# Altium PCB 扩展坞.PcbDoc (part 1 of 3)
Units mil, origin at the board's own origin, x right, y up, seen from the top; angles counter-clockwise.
Board outline 3543.31 x 1968.5 mil, 4 copper layers (Top Layer 1, Layer1, Layer2, Bottom Layer 1), stack 62.337 mil thick; 191 components, 182 nets, 737 pads, 256 vias.
Unrouted connection lines stored in the file: 242.
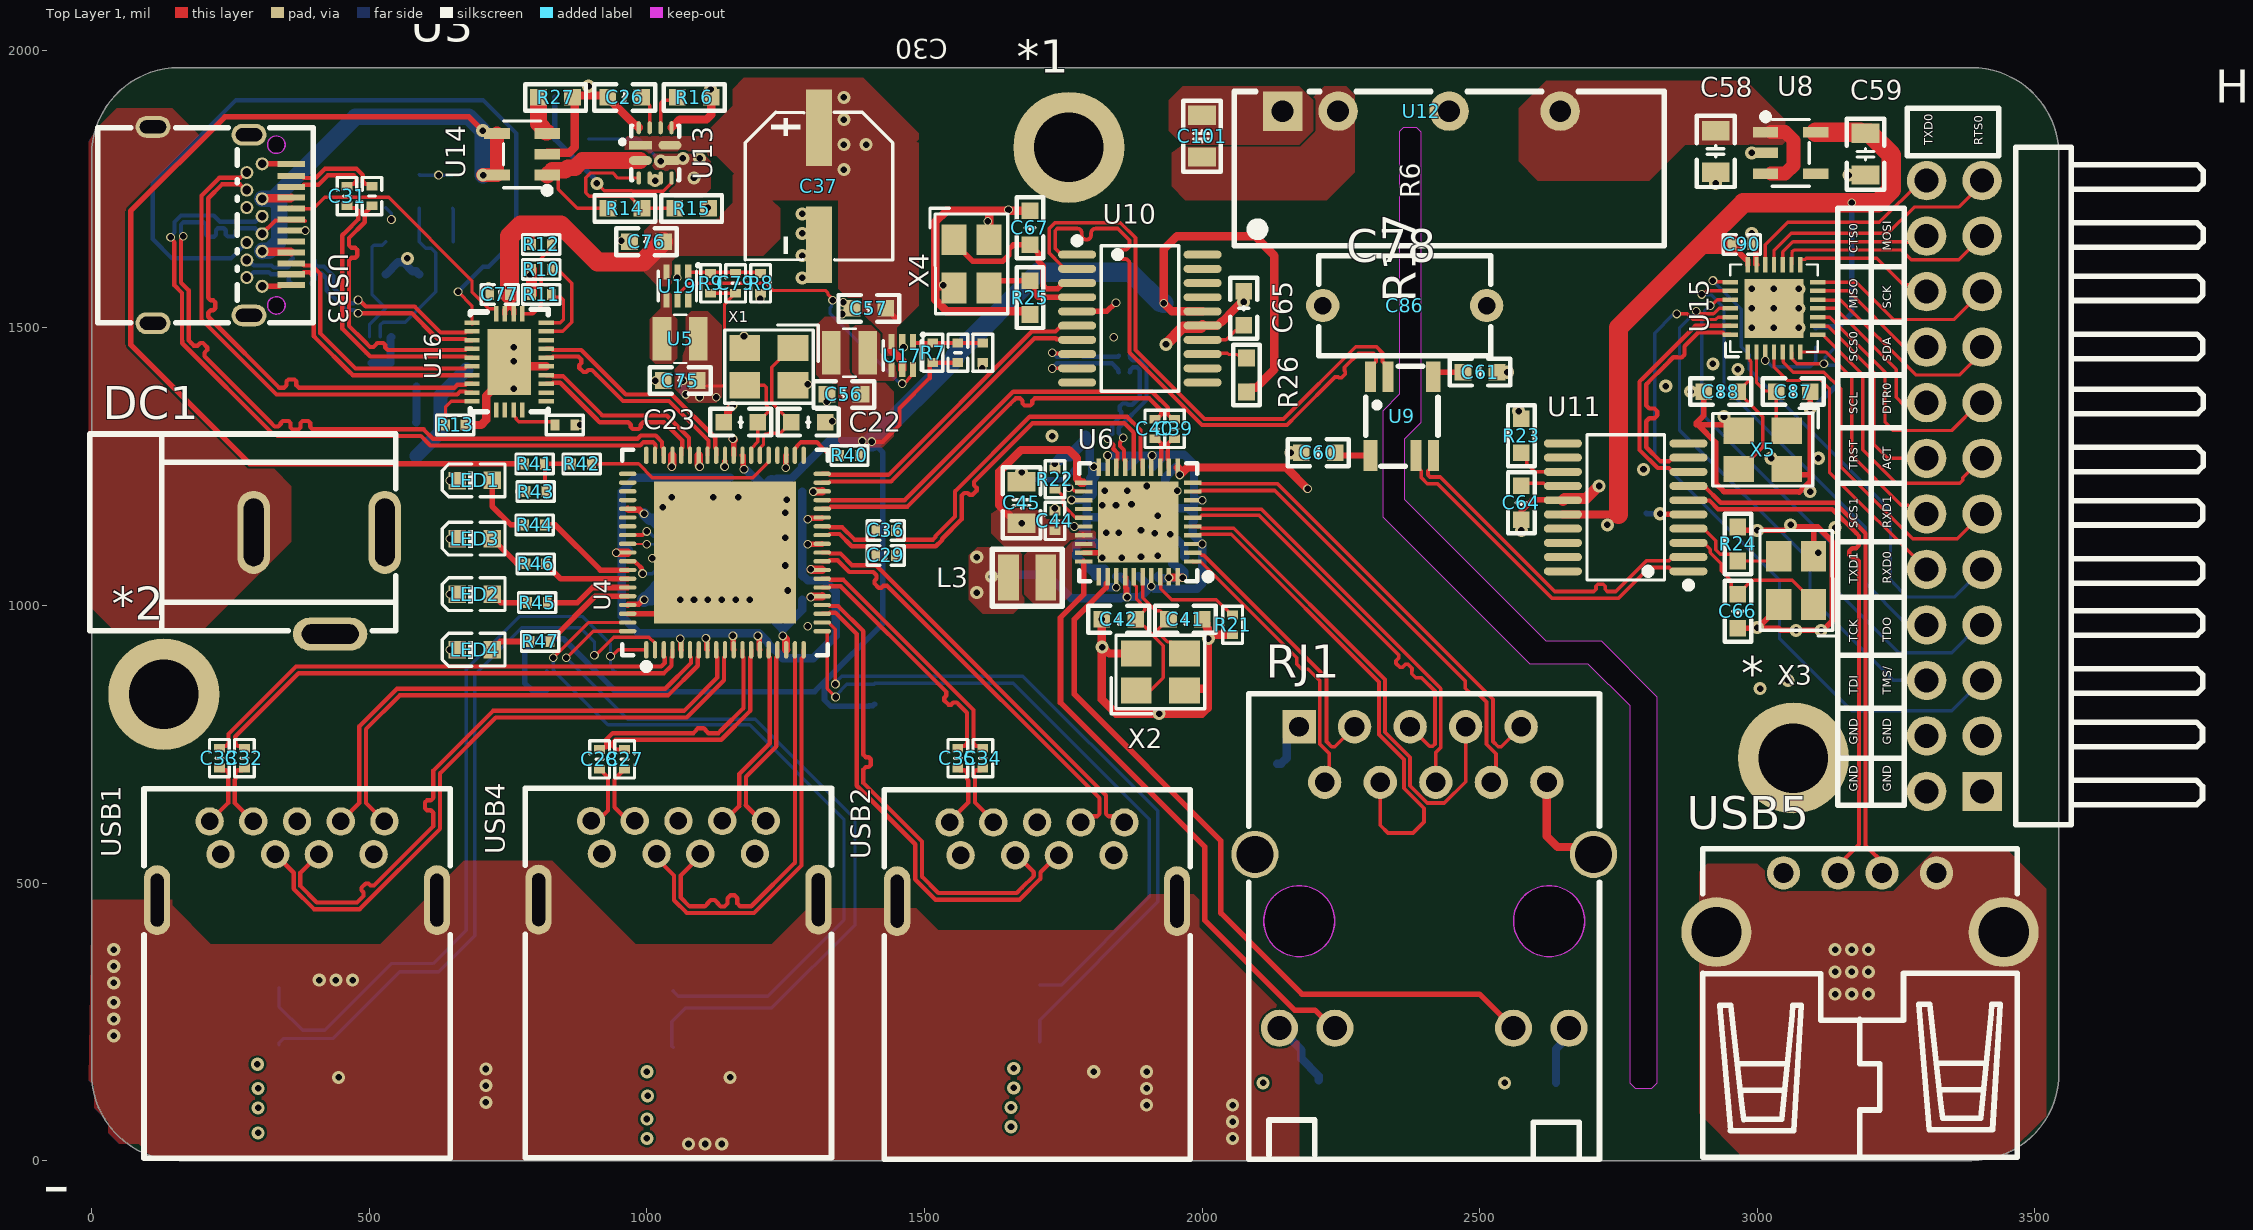
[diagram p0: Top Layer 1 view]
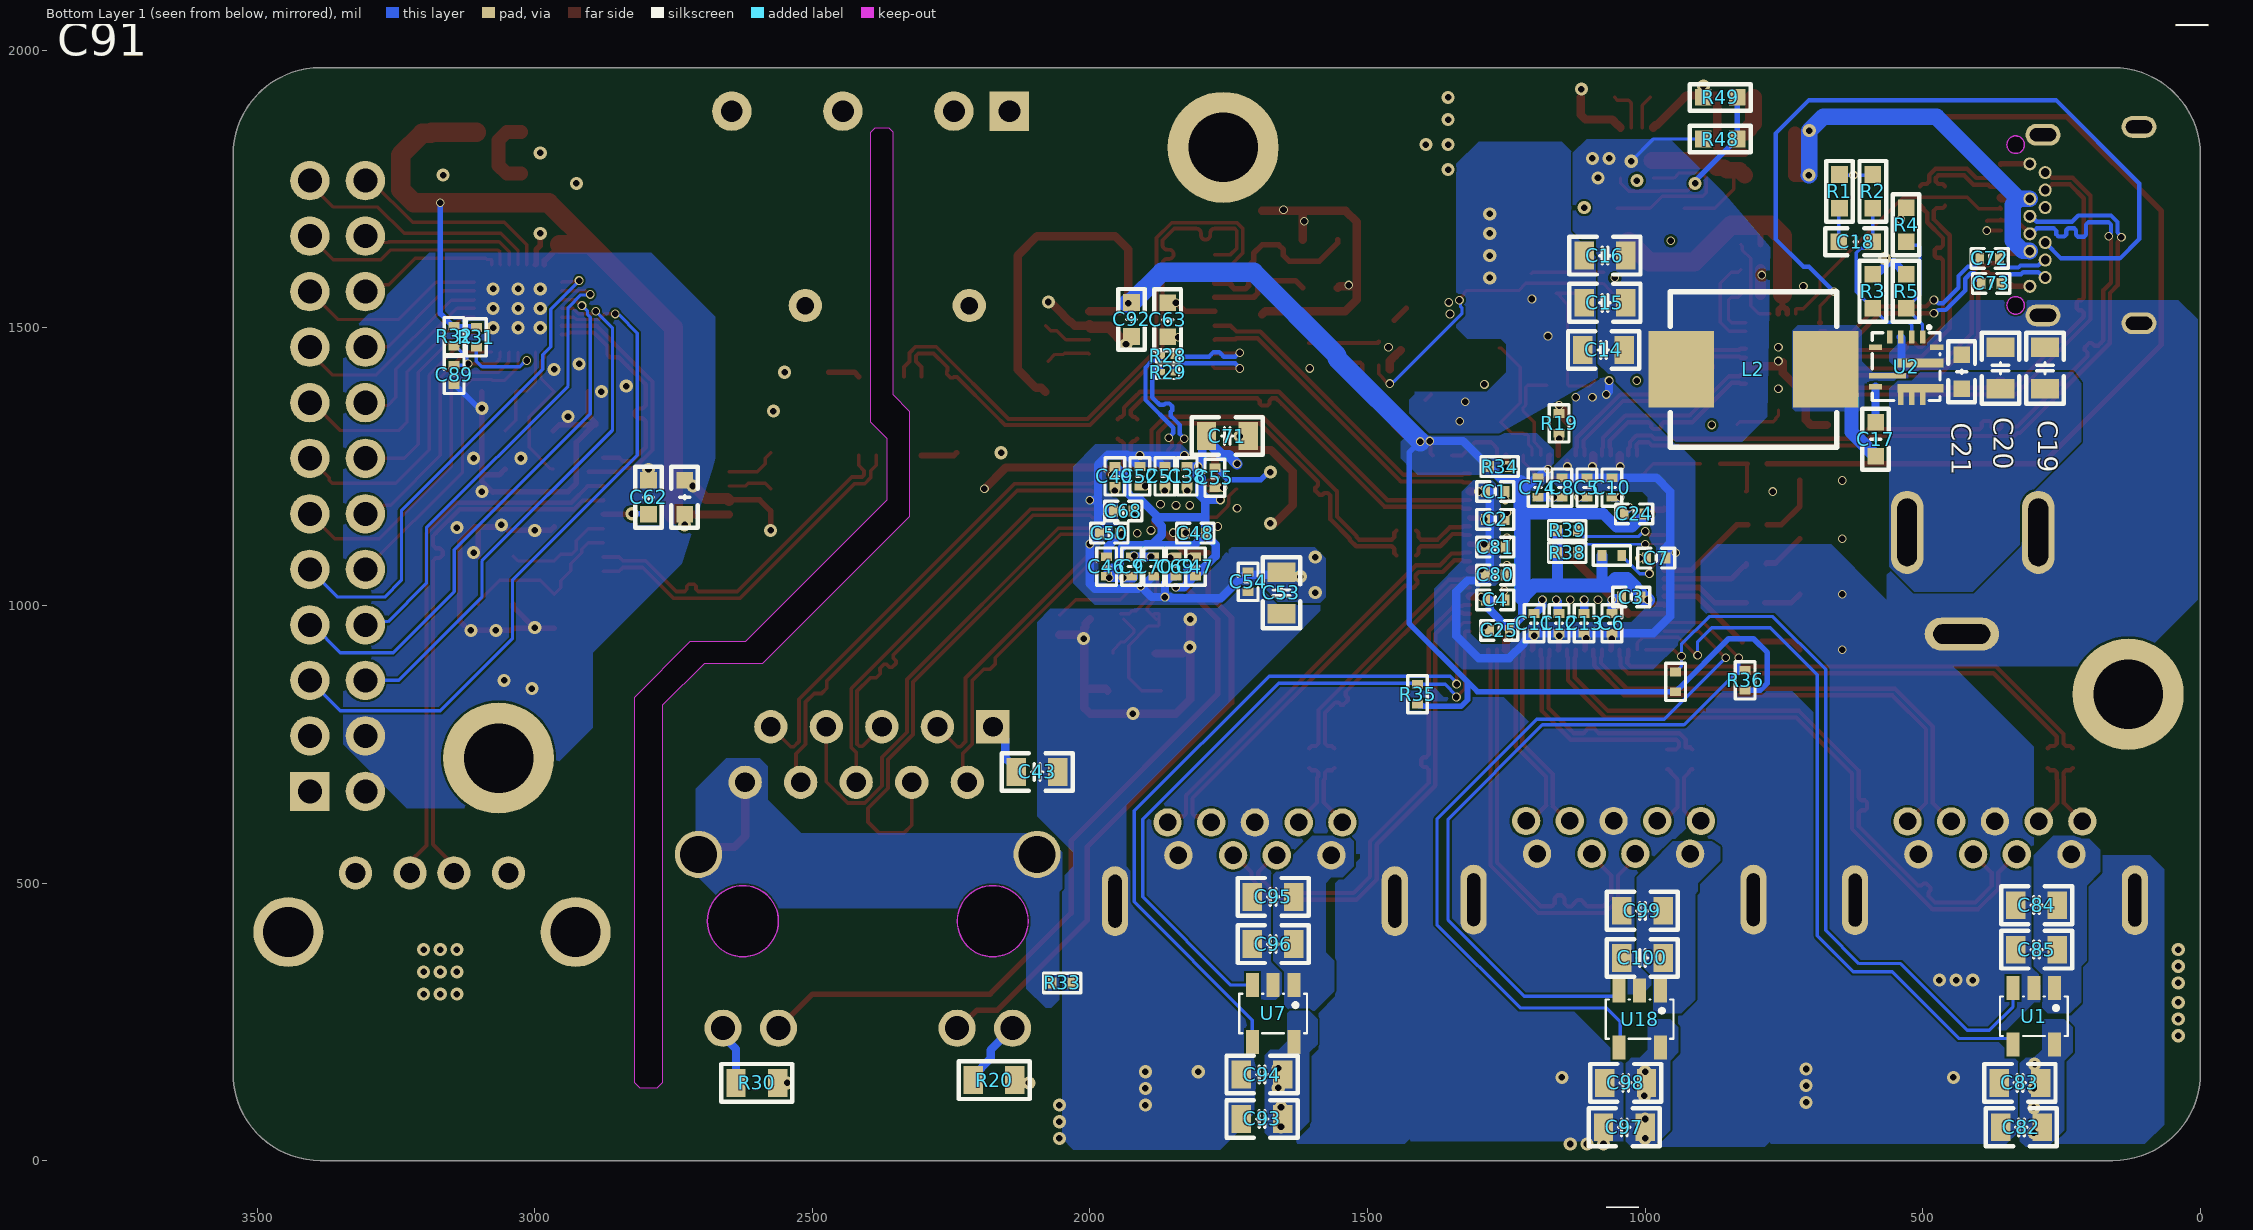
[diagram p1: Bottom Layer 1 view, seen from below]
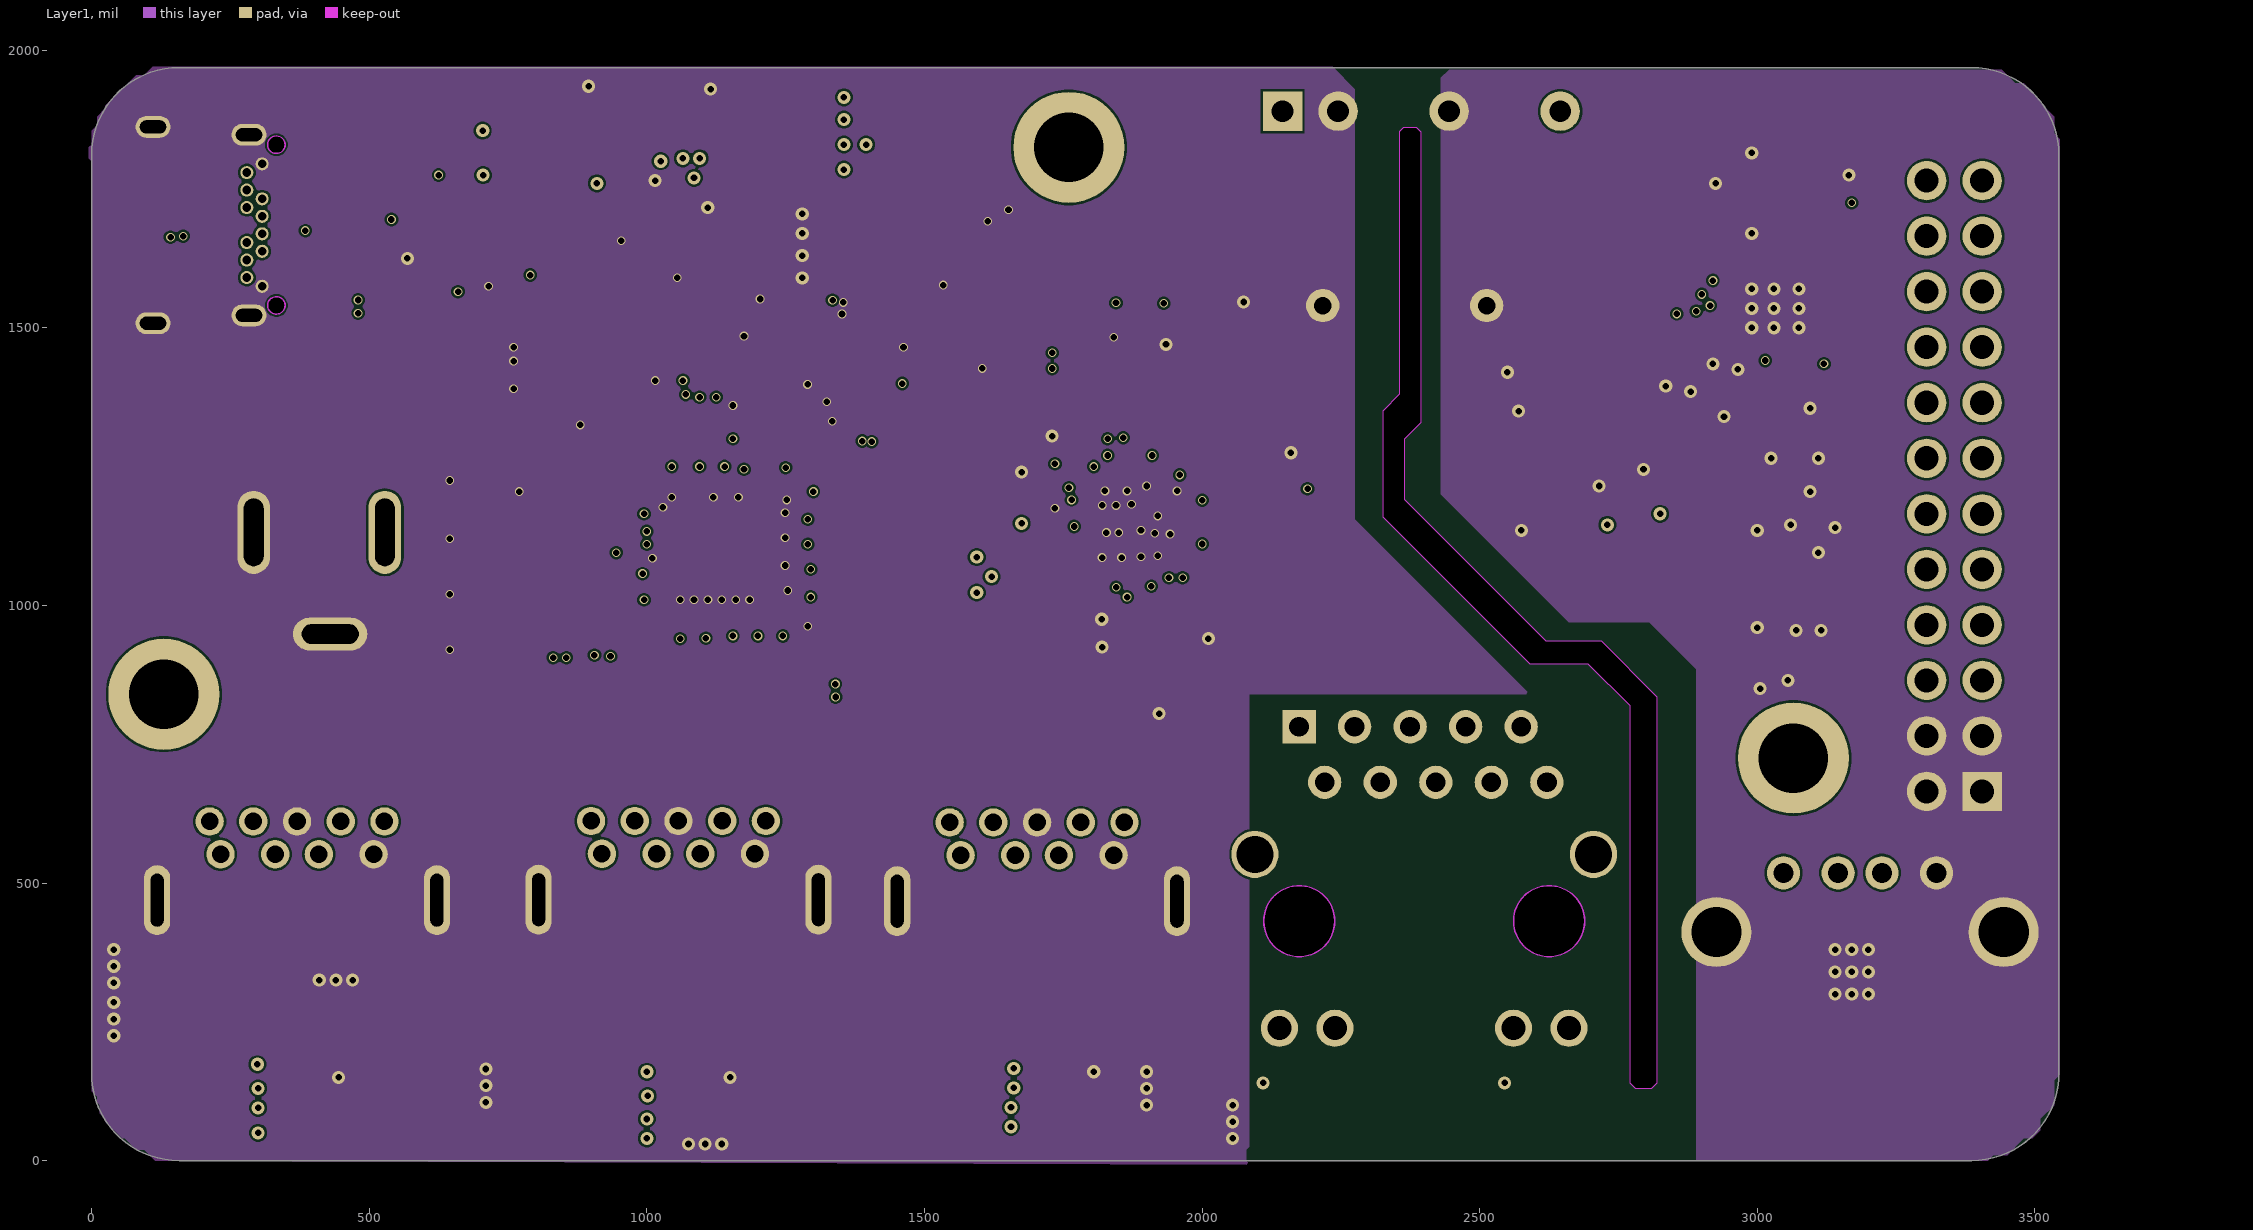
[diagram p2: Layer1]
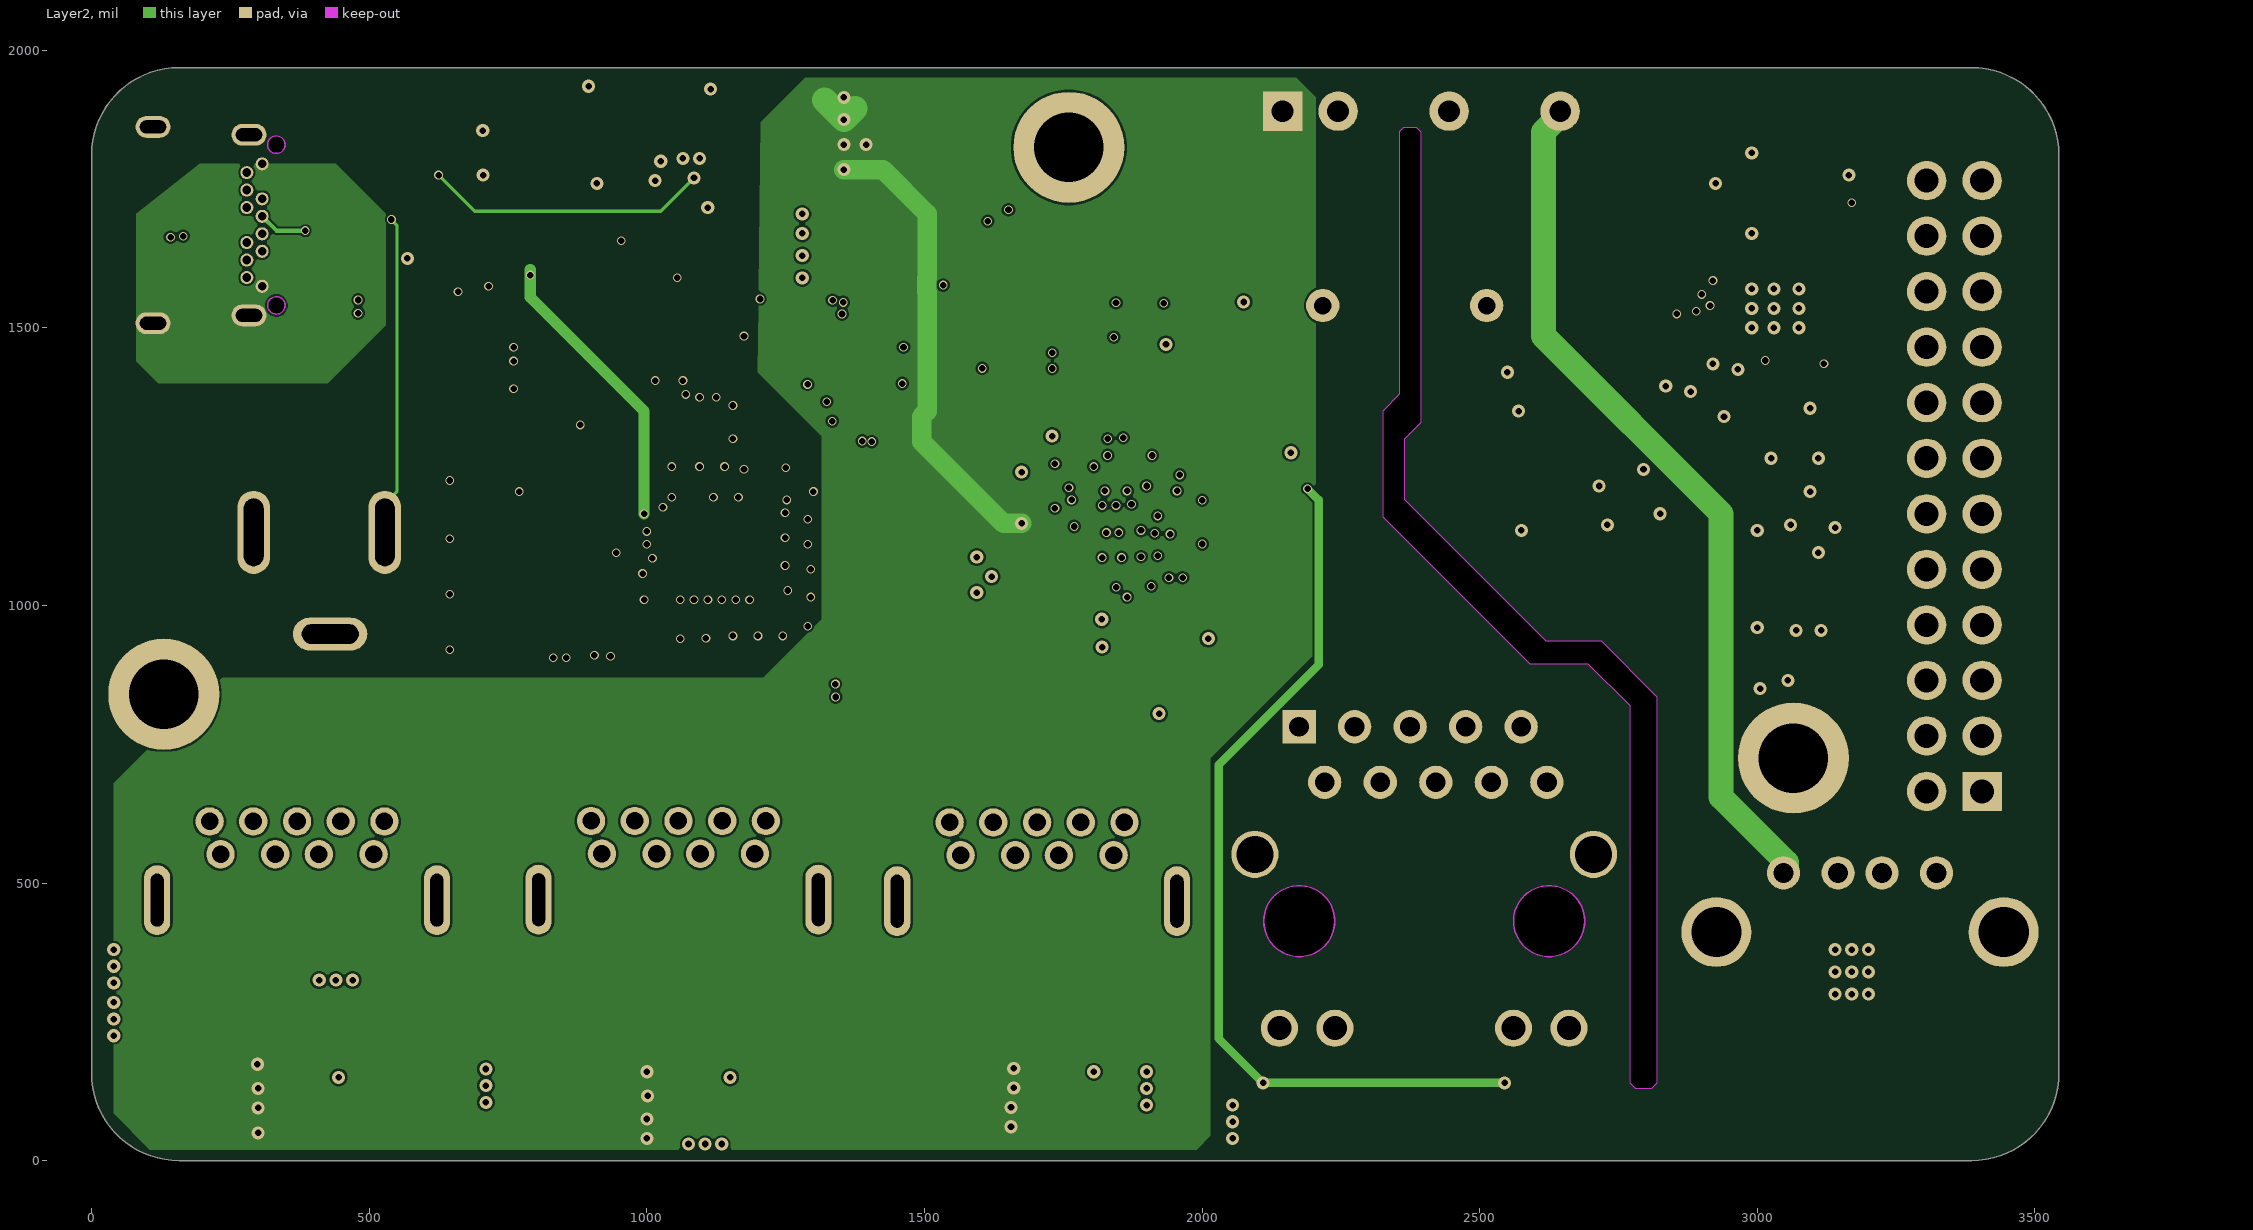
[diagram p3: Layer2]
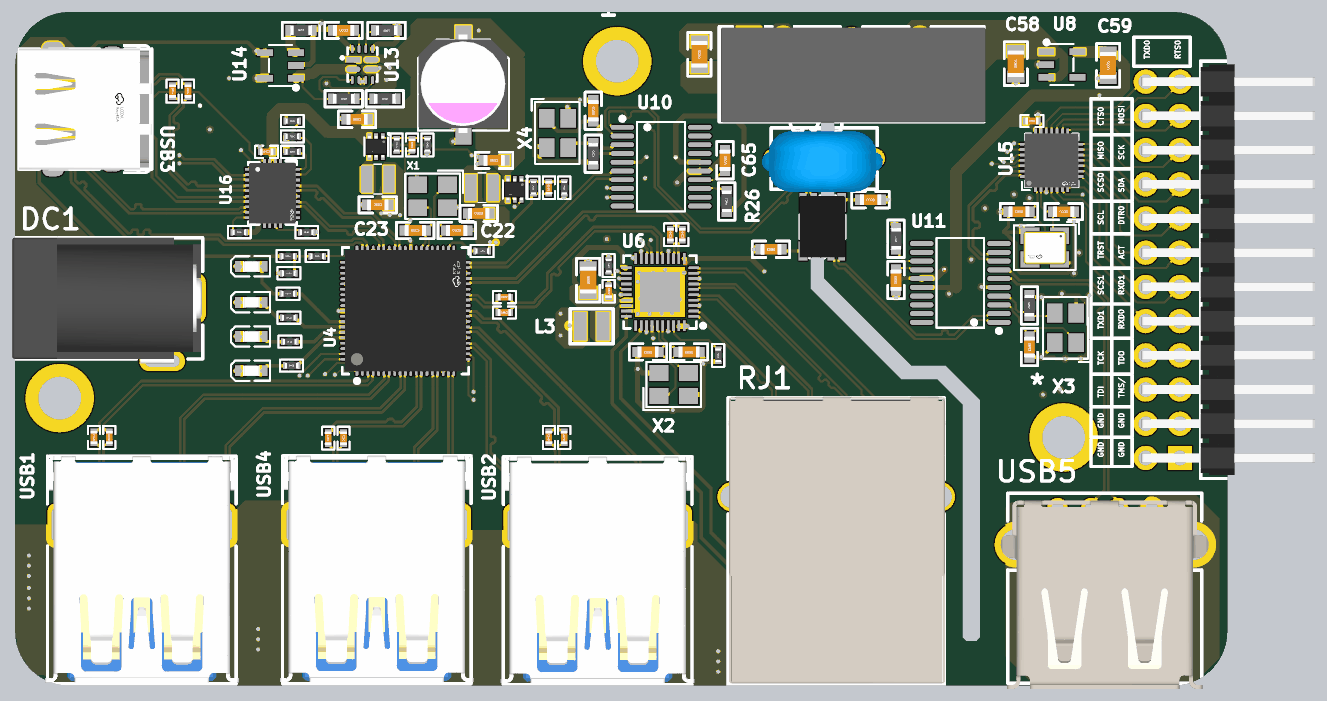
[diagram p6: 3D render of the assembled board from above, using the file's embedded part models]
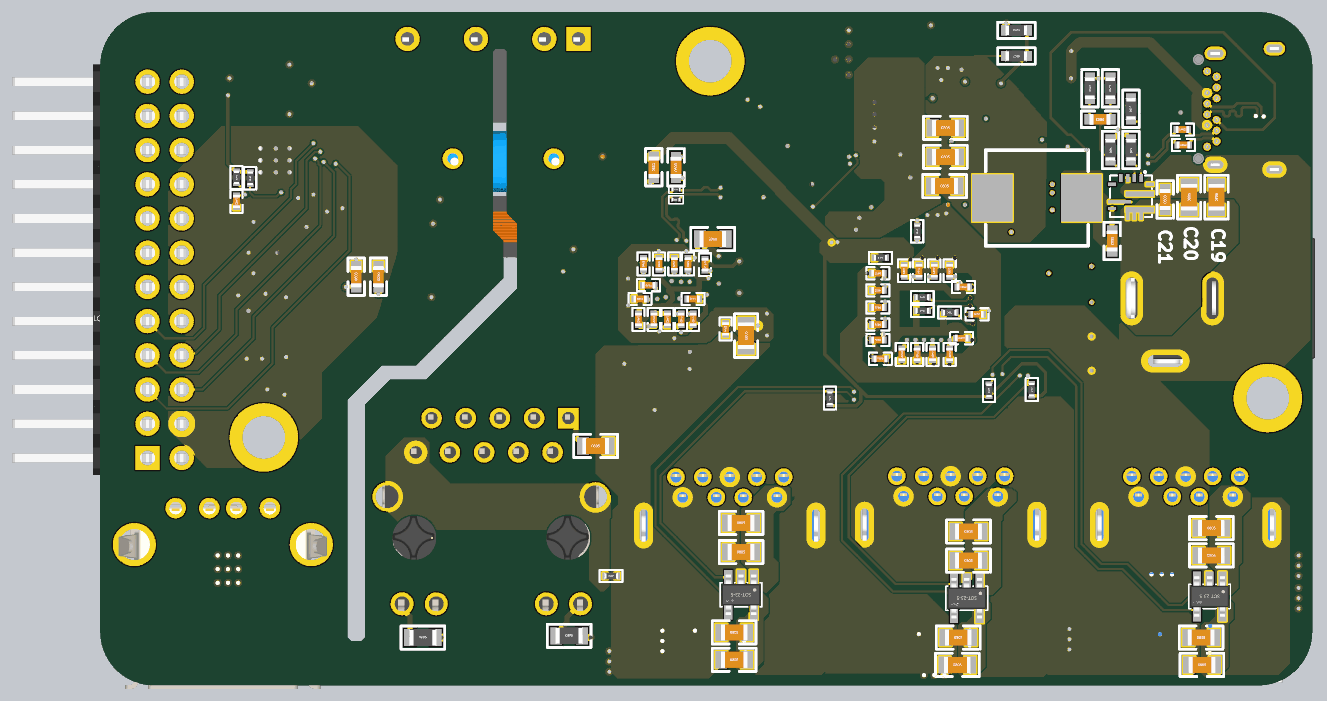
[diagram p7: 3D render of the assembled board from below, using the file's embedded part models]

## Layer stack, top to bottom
Top Solder: solder mask 0.4, Solder Resist, Dk 3.5
Top Layer 1: signal copper 1.378
Dielectric 2: prepreg 2.8, PP-006, Dk 4.1
Layer1: signal copper 1.4
Dielectric 1: dielectric 51.1811, FR-4, Dk 4.8
Layer2: signal copper 1.4
Dielectric 3: prepreg 2.8, PP-006, Dk 4.1
Bottom Layer 1: signal copper 1.378
Bottom Solder: solder mask 0.4, Solder Resist, Dk 3.5

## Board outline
0,157.48 0,1811.02 cw(c157.48,1811.02) 157.48,1968.5 3385.83,1968.5 cw(c3385.83,1811.02) 3543.31,1811.02 3543.31,157.48 cw(c3385.83,157.48) 3385.83,0 157.48,0 cw(c157.48,157.48)
cut-out: 2365,1240 2365,1300 2395,1330 2395,1852.09 2387.09,1860 2362.09,1860 2355,1852.91 2355,1380 2325,1350 2325,1160 2590,895 2695,895 2770,820 2770,140 2780,130 2810,130 2820,140 2820,835 2720,935 2620,935 2365,1190

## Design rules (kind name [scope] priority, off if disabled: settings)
Clearance [All] p1: gap=4 ignorepadtopadclearanceinfootprint=FALSE except(0: Arc-Hole Track-Hole SMDPad-Hole THPad-Hole Via-Hole Fill-Hole Poly-Hole Region-Hole Text-Hole)
ComponentClearance [All] p1: gap=4 collisioncheckmode=3 verticalgap=10 showdistances=FALSE
DiffPairsRouting DiffPair_DiffPairsRouting [InDifferentialPair('No Differential Pair')] p1: maxlimit=30 minlimit=10 mostfreqgap=10 toplayer_minwidth=15 toplayer_maxwidth=30 toplayer_prefwidth=15 midlayer1_minwidth=15 midlayer1_maxwidth=30 midlayer1_prefwidth=15 midlayer2_minwidth=15 midlayer2_maxwidth=30 midlayer2_prefwidth=15 bottomlayer_minwidth=15 bottomlayer_maxwidth=30 bottomlayer_prefwidth=15 maxuncoupledlength=500
DiffPairsRouting DiffPairsRouting_90 [InDifferentialPairClass('90ohm')] p2: maxlimit=40 minlimit=4 mostfreqgap=4.26 toplayer_minwidth=4 toplayer_maxwidth=30 toplayer_prefwidth=7.74 midlayer1_minwidth=4 midlayer1_maxwidth=30 midlayer1_prefwidth=7.74 midlayer2_minwidth=4 midlayer2_maxwidth=30 midlayer2_prefwidth=7.74 bottomlayer_minwidth=4 bottomlayer_maxwidth=30 bottomlayer_prefwidth=7.74 maxuncoupledlength=500
DiffPairsRouting DiffPairsRouting_100 [InDifferentialPairClass('100ohm')] p3: maxlimit=10 minlimit=4 mostfreqgap=10 toplayer_prefgap=5.3 toplayer_minwidth=4 toplayer_maxwidth=30 toplayer_prefwidth=6.7 midlayer1_mingap=10 midlayer1_minwidth=15 midlayer1_maxwidth=15 midlayer1_prefwidth=15 midlayer2_mingap=10 midlayer2_minwidth=15 midlayer2_maxwidth=15 midlayer2_prefwidth=15 bottomlayer_prefgap=5.3 bottomlayer_minwidth=4 bottomlayer_maxwidth=30 bottomlayer_prefwidth=6.7 maxuncoupledlength=500
HoleSize [All] p1: absolutevalues=TRUE maxlimit=500 minlimit=1 maxpercent=80.000 minpercent=20.000
HoleToHoleClearance [All] p1: gap=10 allowstackedmicrovias=FALSE
MatchedLengths [InDifferentialPairClass('90ohm')] p1: tolerance=5 checknetsindiffpair=TRUE checkdiffpairvsdiffpair=FALSE checkxsignals=FALSE checkothers=FALSE
MatchedLengths DiffPair_MatchedLengths [InDifferentialPairClass('100ohm')] p2: tolerance=5 checknetsindiffpair=TRUE checkdiffpairvsdiffpair=FALSE checkxsignals=FALSE checkothers=FALSE
MinimumSolderMaskSliver [All] p1: minsoldermaskwidth=0
PolygonConnect [All] p1: connectstyle=Direct reliefconductorwidth=10 reliefentries=4 polygonreliefangle="90 Angle" airgapwidth=10
RoutingVias [All] p1: holewidth=11.81 width=15.75 viastyle="Through Hole" minholewidth=11.81 minwidth=15.75 maxholewidth=23.62 maxwidth=50
SilkToSolderMaskClearance [IsPad] p1: minsilkscreentomaskgap=2 clearancetoexposedcopper=TRUE
SolderMaskExpansion [All] p1: expansion=4 istentingtop=FALSE
Width [All] p1: maxlimit=100 minlimit=4 preferedwidth=10 minimp=50.000000 maximp=50.000000 favimp=50.000000
24 further rules are at their usual default settings.

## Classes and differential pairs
differential pair class 100ohm: HS2 INX MDI0 MDI1 MDI2 MDI3 NewDifferentialPair2 X X_IN
differential pair class 90ohm: AC_SS2_RX AC_SS2_TX AC_SS3_TX AC_SS4_TX AC_TX1 AC_UP_TX DU DU2 ETH ETH1 ETH1_D ETH_D HS2 HSD0 HSD1 HSD2 HSD3 HSD4 ISO_USB1 ISO_USB2 NewDifferentialPair2 P1C_SS_RX P1C_SS_TX RX0 RX1 RX2 RX3 RX4 SS1_RX SS1_TX SS2_RX SS2_TX SS3_RX SS3_TX SS4_RX SS4_TX TX0 TX1 TX2 TX3 TX4 UP_RX UP_TX
component class ISO_USB: C58 C59 C60 C61 C62 C63 C64 C65 C66 C67 C86 C87 C88 C89 C90 C91 C92 C101 H1 R23 R24 R25 R26 R31 R32 U8 U9 U10 U11 U12 U15 USB5 X3 X4 X5
component class ETH: C9 C29 C36 C38 C39 C40 C41 C42 C43 C44 C45 C46 C47 C48 C49 C50 C51 C52 C53 C54 C55 C68 C69 C70 C71 L3 R20 R21 R22 R28 R29 R30 R33 RJ1 U6 X2
component class Power: C14 C15 C16 C17 C18 C19 C20 C21 C26 C37 C56 C57 C75 C76 C78 C79 DC1 L2 R1 R2 R3 R4 R5 R6 R7 R8 R9 R14 R15 R16 R27 R48 R49 U2 U4 U5 U13 U14 U17 U19
component class VL822: * *1 *2 C1 C2 C3 C4 C5 C6 C7 C8 C10 C11 C12 C13 C22 C23 C24 C25 C27 C28 C30 C31 C32 C33 C34 C35 C72 C73 C74 C77 C80 C81 C82 C83 C84 C85 C93 C94 C95 C96 C97 C98 C99 C100 LED1 LED2 LED3 LED4 R10 R11 R12 R13 R17 R18 R19 R34 R35 R36 R37 R38 R39 R40 R41 R42 R43 R44 R45 R46 R47 U1 U3 U7 U16 U18 USB1 USB2 USB3 USB4 X1
differential pair NewDifferentialPair1: +AC_SS1_TX_P -AC_SS1_TX_N
differential pair X: +X_P -X_N
differential pair TX4: +TX4_P -TX4_N
differential pair TX3: +TX3_P -TX3_N
differential pair TX2: +TX2_P -TX2_N
differential pair TX1: +TX1_P -TX1_N
differential pair RX4: +RX4_P -RX4_N
differential pair RX3: +RX3_P -RX3_N
differential pair RX2: +RX2_P -RX2_N
differential pair RX1: +RX1_P -RX1_N
differential pair INX: +INX_P -INX_N
differential pair HSD4: +HSD4_P -HSD4_N
differential pair HSD3: +HSD3_P -HSD3_N
differential pair HSD2: +HSD2_P -HSD2_N
differential pair HSD1: +HSD1_P -HSD1_N
differential pair ETH_D: +ETH_D_P -ETH_D_N
differential pair ETH1_D: +ETH1_D_P -ETH1_D_N
differential pair DU: +DU_P -DU_N
differential pair DU2: +DU2_P -DU2_N
differential pair AC_TX1: +AC_TX1_P -AC_TX1_N
differential pair TX0: +TX0_P -TX0_N
differential pair RX0: +RX0_P -RX0_N
differential pair HSD0: +HSD0_P -HSD0_N
differential pair MDI3: +MDI3_P -MDI3_N
differential pair MDI2: +MDI2_P -MDI2_N
differential pair MDI1: +MDI1_P -MDI1_N
differential pair MDI0: +MDI0_P -MDI0_N
differential pair AC_SS2_TX: +AC_SS2_TX_P -AC_SS2_TX_N
differential pair AC_SS2_RX: +AC_SS2_RX_P -AC_SS2_RX_N
differential pair AC_SS4_TX: +AC_SS4_TX_P -AC_SS4_TX_N
differential pair AC_SS3_TX: +AC_SS3_TX_P -AC_SS3_TX_N
differential pair SS1_RX: +SS1_RX_P -SS1_RX_N
differential pair P1C_SS_RX: +P1C_SS_RX_P -P1C_SS_RX_N
differential pair SS1_TX: +SS1_TX_P -SS1_TX_N
differential pair AC_PC1_TX: +AC_P1C_SS_TX_P -AC_P1C_SS_TX_N
differential pair P1C_SS_TX: +P1C_SS_TX_P -P1C_SS_TX_N

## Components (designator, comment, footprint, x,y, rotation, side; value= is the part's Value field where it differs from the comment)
* "M3" "M3 125X200" 3065,725 r0 top
*1 "M3" "M3 125X200" 1760,1825 r0 top
*2 "M3" "M3 125X200" 130,840 r0 top
C1 "100nF" "C 0402_L" 1270,1205 r0 bottom
C2 "100nF" "C 0402_L" 1270,1155 r0 bottom
C3 "100nF" "C 0402_L" 1025,1015 r180 bottom
C4 "100nF" "C 0402_L" 1270,1010 r0 bottom
C5 "100nF" "C 0402_L" 1105,1212.29 r90 bottom
C6 "100nF" "C 0402_L" 1060,967.71 r270 bottom
C7 "100nF" "C 0402_L" 980,1085 r180 bottom
C8 "100nF" "C 0402_L" 1150,1212.29 r90 bottom
C9 "100nF" "C 0402_L" 1925,1070 r270 bottom
C10 "100nF" "C 0402_L" 1060,1212.29 r90 bottom
C11 "100nF" "C 0402_L" 1200,967.71 r270 bottom
C12 "100nF" "C 0402_L" 1155,967.71 r270 bottom
C13 "100nF" "C 0402_L" 1110,967.71 r270 bottom
C14 "22uF" "C 0805_L" 1075,1460 r180 bottom
C15 "22uF" "C 0805_L" 1072.4,1545 r180 bottom
C16 "22uF" "C 0805_L" 1072.4,1630 r180 bottom
C17 "100nF" "C 0603_L" 585,1299.41 r270 bottom
C18 "100pF" "C 0603_L" 620.59,1655 r0 bottom
C19 "10uF" "C 0805_L" 280,1427.4 r90 bottom
C20 "10uF" "C 0805_L" 360,1427.4 r90 bottom
C21 "100nF" "C 0603_L" 430,1420.59 r90 bottom
C22 "20pF" "C 0603_L" 1290.59,1330 r0 top
C23 "20pF" "C 0603_L" 1169.41,1330 r0 top
C24 "100nF" "C 0402_L" 1020,1165 r180 bottom
C25 "100nF" "C 0402_L" 1262.71,955 r180 bottom
C26 "100nF" "C 0603_L" 960,1915 r0 top
C27 "100nF" "C 0402_L" 960,722.72 r90 top
C28 "100nF" "C 0402_L" 915,722.72 r90 top
C29 "100nF" "C 0402_L" 1430,1090 r0 top
C30 "100nF" "C 0402_L" 505,1737.28 r270 top
C31 "100nF" "C 0402_L" 460,1737.28 r270 top
C32 "100nF" "C 0402_L" 275,725 r90 top
C33 "100nF" "C 0402_L" 230,725 r90 top
C34 "100nF" "C 0402_L" 1605,725 r90 top
C35 "100nF" "C 0402_L" 1560,725 r90 top
C36 "100nF" "C 0402_L" 1430,1135 r0 top
C37 "ma25v220m6x8" CAP-SMD_BD6.3-L6.6-W6.6-LS7.3-FD 1310,1755 r270 top value=220uF
C38 "100nF" "C 0402_L" 1825,1232.29 r90 bottom
C39 "100nF" "C 0402_L" 1950,1317.71 r270 top
C40 "100nF" "C 0402_L" 1915,1317.71 r270 top
C41 "20pF" "C 0603_L" 1970,975 r180 top
C42 "20pF" "C 0603_L" 1850,975 r180 top
C43 "100nF" "C 0805_L" 2095,700 r180 bottom
C44 "100nF" "C 0402_L" 1735,1152.28 r270 top
C45 "10uF" "C 0805_L" 1675,1185 r270 top
C46 "100nF" "C 0402_L" 1970,1070 r270 bottom
C47 "100nF" "C 0402_L" 1810,1070 r270 bottom
C48 "100nF" "C 0402_L" 1810,1130 r180 bottom
C49 "100nF" "C 0402_L" 1955,1232.29 r90 bottom
C50 "100nF" "C 0402_L" 1965,1130 r0 bottom
C51 "100nF" "C 0402_L" 1865,1232.29 r90 bottom
C52 "100nF" "C 0402_L" 1910,1232.29 r90 bottom
C53 "10uF" "C 0805_L" 1655,1022.6 r90 bottom
C54 "100nF" "C 0402_L" 1715,1042.29 r90 bottom
C55 "100nF" "C 0402_L" 1775,1230 r270 bottom
C56 "22uF" "C 0603_L" 1355,1380 r0 top
C57 "22uF" "C 0603_L" 1400,1535 r0 top
C58 "10uF" "C 0805_L" 2925,1817.6 r90 top
C59 "10uF" "C 0805_L" 3195,1812.6 r90 top
C60 "100nF" "C 0603_L" 2209.41,1275 r180 top
C61 "100nF" "C 0603_L" 2500.59,1420 r180 top
C62 "1uF" "C 0603_L" 2795,1195 r90 bottom
C63 "1uF" "C 0603_L" 1860,1514.41 r90 bottom
C64 "100nF" "C 0603_L" 2575,1185 r90 top
C65 "100nF" "C 0603_L" 2075,1535 r270 top
C66 "30pF" "C 0603_L" 2965,989.41 r270 top
C67 "30pF" "C 0603_L" 1690,1680 r90 top
C68 "100nF" "C 0402_L" 1940,1170 r0 bottom
C69 "100nF" "C 0402_L" 1845,1070 r270 bottom
C70 "100nF" "C 0402_L" 1885,1070 r270 bottom
C71 "10uF" "C 0805_L" 1752.6,1305 r0 bottom
C72 "100nF" "C 0402_L" 379.6,1625 r180 bottom
C73 "100nF" "C 0402_L" 376.88,1580 r180 bottom
C74 "100nF" "C 0402_L" 1193.03,1212.29 r90 bottom
C75 "22uF" "C 0603_L" 1060,1405 r0 top
C76 "22uF" "C 0603_L" 999.41,1655 r0 top
C77 "100nF" "C 0402_L" 735,1560 r0 top
C78 "22pF" "C 0402_L" 1560,1455 r90 top
C79 "22pF" "C 0402_L" 1160,1580 r90 top
C80 "100nF" "C 0402_L" 1270,1055 r0 bottom
C81 "100nF" "C 0402_L" 1270,1105 r0 bottom
C82 "22uF" "C 0805_L" 322.4,60 r180 bottom
C83 "22uF" "C 0805_L" 325,140 r180 bottom
C84 "22uF" "C 0805_L" 295,460 r180 bottom
C85 "22uF" "C 0805_L" 295,380 r180 bottom
C86 "q222m060110fq55250l7579" CAP-TH_L8.0-W4.5-P7.50-D0.6 2365,1540 r0 top value=2.2nF
C87 "20pF" "C 0603_L" 3065,1385 r180 top
C88 "20pF" "C 0603_L" 2934.41,1385 r180 top
C89 "100nF" "C 0402_L" 3145,1415 r270 bottom
C90 "100nF" "C 0402_L" 2972.28,1650 r180 top
C91 "100nF" "C 0603_L" 2730,1195 r270 bottom
C92 "100nF" "C 0603_L" 1925,1515 r90 bottom
C93 "22uF" "C 0805_L" 1690,75 r180 bottom
C94 "22uF" "C 0805_L" 1690,155 r180 bottom
C95 "22uF" "C 0805_L" 1670,475 r180 bottom
C96 "22uF" "C 0805_L" 1670,390 r180 bottom
C97 "22uF" "C 0805_L" 1037.6,60 r180 bottom
C98 "22uF" "C 0805_L" 1035,140 r180 bottom
C99 "22uF" "C 0805_L" 1005,450 r180 bottom
C100 "22uF" "C 0805_L" 1005,365 r180 bottom
C101 "10uF" "C 0805_L" 2000,1845 r90 top
DC1 "dc-005-a200" DC-IN-TH_DC-005-A200 410,1040 r0 top
H1 "x6521wr-2x12h-c60d30" HDR-TH_24P-P2.54-H-M-R2-C12-S2.54 3355,1215 r90 top
L2 "pcr0630-3r3-m" IND-SMD_L7.5-W6.6 805,1425 r0 bottom
L3 "smms252012-2r2m" IND-SMD_L2.5-W2.0_AFE252010S 1685,1050 r180 top value=2.2uH
LED1 "f.0603.00025/p2-0603g1ts2-06t-002" LED0603-RD_GREEN 690,1225 r0 top
LED2 "f.0603.00025/p2-0603g1ts2-06t-002" LED0603-RD_GREEN 690,1020 r0 top
LED3 "f.0603.00025/p2-0603g1ts2-06t-002" LED0603-RD_GREEN 690,1120 r0 top
LED4 "f.0603.00025/p2-0603g1ts2-06t-002" LED0603-RD_GREEN 690,920 r0 top
R1 "20K" "R 0603_L" 650,1745.59 r270 bottom
R2 "110K" "R 0603_L" 590,1745.59 r90 bottom
R3 "15K" "R 0603_L" 590,1565.59 r270 bottom
R4 "169K" "R 0603_L" 530,1685.59 r90 bottom
R5 "36.1K" "R 0603_L" 530,1565.59 r270 bottom
R6 "100K" "R 0402_L" 1605,1455 r270 top
R7 "450K" "R 0402_L" 1515,1455 r90 top
R8 "100k" "R 0402_L" 1205,1580 r270 top
R9 "75K" "R 0402_L" 1115,1580 r90 top
R10 "10K" "R 0402_L" 810,1605 r180 top
R11 "10K" "R 0402_L" 810,1560 r180 top
R12 "10K" "R 0402_L" 810,1650 r180 top
R13 "20.5K" "R 0402_L" 655,1325 r180 top
R14 "10K" "R 0603_L" 960.59,1715 r180 top
R15 "3.3K" "R 0603_L" 1080.59,1715 r180 top
R16 "0R" "R 0603_L" 1085.59,1915 r180 top
R17 "10K" "R 0402_L" 852.28,1325 r180 top
R18 "4.7K" "R 0402_L" 945,862.29 r90 bottom
R19 "12.4K" "R 0402_L" 1155,1327.71 r270 bottom
R20 "1K" "R 0805_L" 2172.6,145 r180 bottom
R21 "2.49K" "R 0402_L" 2055,965 r90 top
R22 "10K" "R 0402_L" 1735,1227.28 r270 top
R23 "5.1K" "R 0603_L" 2575,1305.59 r90 top
R24 "4.7M" "R 0603_L" 2965,1110.59 r90 top
R25 "4.7M" "R 0603_L" 1690,1554.41 r270 top
R26 "5.1K" "R 0603_L" 2080,1415 r90 top
R27 "10K" "R 0603_L" 835.59,1915 r0 top
R28 "0R" "R 0201_L" 1859.84,1450 r180 bottom
R29 "0R" "R 0201_L" 1860,1420 r180 bottom
R30 "1K" "R 0805_L" 2600,140 r180 bottom
R31 "10K" "R 0402_L" 3105,1482.71 r270 bottom
R32 "0R" "R 0402_L" 3145,1485 r270 bottom
R33 "0R" "R 0402_L" 2050,320 r180 bottom
R34 "4.7K" "R 0402_L" 1262.28,1250 r180 bottom
R35 "4.7K" "R 0402_L" 1410,840 r90 bottom
R36 "4.7K" "R 0402_L" 820,865 r90 bottom
R37 "4.7K" "R 0402_L" 1060,1090 r180 bottom
R38 "4.7K" "R 0402_L" 1140,1095 r180 bottom
R39 "4.7K" "R 0402_L" 1140,1135 r180 bottom
R40 "4.7K" "R 0402_L" 1365,1270 r180 top
R41 "4.7K" "R 0402_L" 797.72,1255 r0 top
R42 "0R" "R 0402_L" 882.72,1255 r0 top
R43 "10K" "R 0402_L" 800,1205 r180 top
R44 "1K" "R 0402_L" 797.72,1145 r0 top
R45 "1K" "R 0402_L" 802.72,1005 r0 top
R46 "1K" "R 0402_L" 800,1075 r0 top
R47 "1K" "R 0402_L" 807.72,935 r0 top
R48 "27K" "R 0603_L" 865,1840 r0 bottom
R49 "10K" "R 0603_L" 865,1915 r180 bottom
RJ1 "hr911130a" RJ45-TH_HR911130A 2400,510 r180 top
U1 "sy6288caac" SOT-23-5_L3.0-W1.7-P0.95-LS2.8-BR 300,260 r90 bottom
U2 "tps56637rpar" VQFN-HR-10_L3.0-W3.0_RPA 530,1430 r270 bottom
U3 "vl822-q7" QFN-76_L9.0-W9.0-P0.40-EP6.3-TL 1140.7,1095.2 r90 top
U4 "ftc252012s1r0mbca" IND-SMD_L2.5-W2.0-VLS252012CX-150M 1365,1455 r180 top
U5 "ftc252012s1r0mbca" IND-SMD_L2.5-W2.0-VLS252012CX-150M 1060,1480 r0 top
U6 "rtl8153b-vb-cg" QFN-40_L5.0-W5.0-P0.40-BL-EP3.7 1885,1150 r90 top
U7 "sy6288caac" SOT-23-5_L3.0-W1.7-P0.95-LS2.8-BR 1670,265 r90 bottom
U8 "rt9013-33gb" SOT-23-5_L3.0-W1.7-P0.95-LS2.8-BL 3060,1815 r270 top
U9 "ga021g00" FILTER-SMD_6P-L4.5-W3.4_GA021G00 2359.91,1340.86 r270 top
U10 "ch318t_c42387966" TSSOP-20_L6.5-W4.4-P0.65-LS6.4-BL 1888.03,1516.61 r270 top
U11 "ch318t_c42387966" TSSOP-20_L6.5-W4.4-P0.65-LS6.4-BL 2763.03,1176.61 r90 top
U12 "b0505s-2wr3_c7465195" PWRM-TH_BXXXXS-2WR3 2395,1890 r0 top value=200kHz~340kHz
U13 "tps2121ruxr" VQFN-HR-12_L2.5-W2.0-P0.50-BL 1015,1815 r270 top
U14 "sy6280aac_c55136" SOT-23-5_L3.0-W1.7-P0.95-LS2.8-BL 775.5,1812.4 r90 top
U15 "ch347f" QFN-28_L4.0-W4.0-P0.40-BL-EP2.7 3030,1535 r0 top
U16 "vl162" MQFN-28_L4.5-W3.5-P0.40-BL-EP 752.13,1438.38 r270 top
U17 "eta3512fsg" SOT-563-6_L1.6-W1.2-P0.5-LS1.6-BL 1460,1450 r180 top
U18 "sy6288caac" SOT-23-5_L3.0-W1.7-P0.95-LS2.8-BR 1010,255 r90 bottom
U19 "eta3512fsg" SOT-563-6_L1.6-W1.2-P0.5-LS1.6-BL 1055,1575 r180 top
USB1 "hc-usb3.0-l168-zj" USB3.0-A-TH_HC-USB3.0-L168-ZJ 370,540 r0 top
USB2 "hc-usb3.0-l168-zj" USB3.0-A-TH_HC-USB3.0-L168-ZJ 1702.8,538.18 r0 top
USB3 "type-c 24p qcht" TYPE-C-SMD_TYPE-C-24P-QCHT 235,1685 r270 top
USB4 "hc-usb3.0-l168-zj" USB3.0-A-TH_HC-USB3.0-L168-ZJ 1056.97,540.86 r0 top
USB5 "af 90° wjdg" USB-A-TH_AF-WJDG 3185,465 r0 top
X1 "x322525mob4si" CRYSTAL-SMD_4P-L3.2-W2.5-BL#1 1220,1430 r180 top value=25MHz
X2 "x322525mob4si" CRYSTAL-SMD_4P-L3.2-W2.5-BL#2 1925,880 r0 top value=25MHz
X3 "x322520msb4si" CRYSTAL-SMD_4P-L3.2-W2.5-BL-2 3070,1045 r90 top value=20MHz
X4 "x322520msb4si" CRYSTAL-SMD_4P-L3.2-W2.5-BL-2 1585,1615 r270 top value=20MHz
X5 "xl2el89coi-111ylc-8m" CRYSTAL-SMD_4P-L3.2-W2.5-BL-1 3010,1280 r180 top value=8MHz

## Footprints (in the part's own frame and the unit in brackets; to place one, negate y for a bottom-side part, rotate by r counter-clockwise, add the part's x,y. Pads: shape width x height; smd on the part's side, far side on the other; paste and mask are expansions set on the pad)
"C 0402_L" [mm] "无极性贴片电容"
  rect 0.4x0.5 smd: 1(-0.45,0) 2(0.45,0)
  silkscreen extent -0.85,-0.45 0.85,0.45, body extent -0.5,-0.26 0.5,0.26, height 0.53
"C 0603_L" [mil]
  rect 30x30 smd: 1(-30.59,0) 2(30.59,0)
  silkscreen extent -55,-24 55,24, body extent -31,-16 31,16, height 32
"C 0805_L" [mil] "无极性贴片电容"
  rect 35x50 smd: 1(-37.4,0) 2(37.4,0)
  silkscreen extent -64,-34 64,34, body extent -39,-24 39,24, height 20
CAP-SMD_BD6.3-L6.6-W6.6-LS7.3-FD [mil]
  rect 137.8x47.2 smd: 1(-105.1,0) 2(105.1,0)
  silkscreen extent -133,-133 133,133, body extent -148,-131 140,129, height 228
CAP-TH_L8.0-W4.5-P7.50-D0.6 [mil]
  round 60 hole 31.5 paste-99999: 1(-147.64,0) 2(147.64,0)
  silkscreen extent -155,-90 155,90, body extent -182,-97 172,80, height 377
CRYSTAL-SMD_4P-L3.2-W2.5-BL#1 [mil]
  rect 55.1x47.2 smd: 1(-43.3,-33.5) 2(43.3,-33.5) 3(43.3,33.4) 4(-43.3,33.4)
  silkscreen extent -89,-75 80,66
CRYSTAL-SMD_4P-L3.2-W2.5-BL#2 [mil]
  rect 55.12x47.24 smd: 1(-43.31,-33.47) 2(43.31,-33.47) 3(43.31,33.47) 4(-43.31,33.47)
  silkscreen extent -89,-75 80,66
CRYSTAL-SMD_4P-L3.2-W2.5-BL-1 [mm]
  rect 1.4x1.2 smd: 1(-1.1,-0.875) 2(1.1,-0.875) 3(1.1,0.875) 4(-1.1,0.875)
  silkscreen extent -2.54,-1.9 2.29,1.65, body extent -1.6,-1.25 1.6,1.25, height 0.71
CRYSTAL-SMD_4P-L3.2-W2.5-BL-2 [mm]
  rect 1.4x1.15 smd: 1(-1.1,-0.8) 2(1.1,-0.8) 3(1.1,0.8) 4(-1.1,0.8)
  silkscreen extent -2.54,-1.9 2.29,1.65
DC-IN-TH_DC-005-A200 [mm]
  oval 1.5x3.8 hole 0.9 slot 3.1 at 90 deg copper offset -0.001,0: 1(3.001,2.325)
  oval 1.5x3.8 hole 0.9 slot 3.1 at 90 deg copper offset 0,0: 2(-3,2.325)
  oval 3.4x1.5 hole 0.9 slot 2.6 at 0 deg copper offset 0,-0.001: 3(0.5,-2.325)
  silkscreen extent -10.5,-2.17 3.5,6.83, body extent -10.62,-2.52 3.43,6.83, height 11
FILTER-SMD_6P-L4.5-W3.4_GA021G00 [mm]
  rect 1.4x0.5 smd paste+0: 1(-1.8,-1.438) 2(-1.8,-0.637) 4(1.8,1.438) 5(1.8,0.637)
  rect 1.4x0.65 smd paste+0: 3(-1.8,1.438) 6(1.8,-1.438)
  silkscreen extent -2.29,-1.65 2.29,1.65, body extent -2.3,-1.7 2.31,1.7, height 3.16
HDR-TH_24P-P2.54-H-M-R2-C12-S2.54 [mm]
  rect 1.778x1.8 hole 1.1: 1(-13.97,-1.27)
  round 1.8 hole 1.1: 2(-13.97,1.27) 3(-11.43,-1.27) 4(-11.43,1.27) 5(-8.89,-1.27) 6(-8.89,1.27) 7(-6.35,-1.27) 8(-6.35,1.27) 9(-3.81,-1.27) 10(-3.81,1.27) 11(-1.27,-1.27) 12(-1.27,1.27) 13(1.27,-1.27) 14(1.27,1.27) 15(3.81,-1.27) 16(3.81,1.27) 17(6.35,-1.27) 18(6.35,1.27) 19(8.89,-1.27) 20(8.89,1.27) 21(11.43,-1.27) 22(11.43,1.27) 23(13.97,-1.27) 24(13.97,1.27)
  silkscreen extent -15.49,-11.38 15.49,-2.81, body extent -15.24,-11.31 15.25,1.59, height 5
IND-SMD_L2.5-W2.0-VLS252012CX-150M [mil]
  rect 33.5x78.7 smd: 1(-32.7,0) 2(32.7,0)
  silkscreen extent -11,-43 11,43
IND-SMD_L2.5-W2.0_AFE252010S [mm]
  rect 0.95x2.1 smd: 1(-0.85,0) 2(0.85,0)
  silkscreen extent -1.6,-1.3 1.6,1.3
IND-SMD_L7.5-W6.6 [mm]
  rect 3x3.5 smd paste+0: 1(-3.302,0) 2(3.302,0)
  silkscreen extent -3.81,-3.56 3.81,3.56
LED0603-RD_GREEN [mm]
  rect 0.8x0.8 smd: 1(-0.799,-0.003) 2(0.799,0.003)
  silkscreen extent -1.49,-0.75 1.39,0.76, body extent -0.81,-0.41 0.81,0.41, height 0.55
"M3 125X200" [mil] "M3螺丝孔，孔125Mil，焊盘200Mil"
  round 200 hole 125: 1(0,0)
MQFN-28_L4.5-W3.5-P0.40-BL-EP [mm]
  rect 0.2x0.7 smd paste-100: 1(-1.8,-1.7) 2(-1.4,-1.7) 3(-1,-1.7) 4(-0.6,-1.7) 5(-0.2,-1.7) 6(0.2,-1.7) 7(0.6,-1.7) 8(1,-1.7) 9(1.4,-1.7) 10(1.8,-1.7) 15(1.8,1.7) 16(1.4,1.7) 17(1,1.7) 18(0.6,1.7) 19(0.2,1.7) 20(-0.2,1.7) 21(-0.6,1.7) 22(-1,1.7) 23(-1.4,1.7) 24(-1.8,1.7)
  rect 0.7x0.2 smd paste-100: 11(2.2,-0.6) 12(2.2,-0.2) 13(2.2,0.2) 14(2.2,0.6) 25(-2.2,0.6) 26(-2.2,0.2) 27(-2.2,-0.2) 28(-2.2,-0.6)
  rect 3x2 smd paste-100: 29(0,0)
  silkscreen extent -2.41,-1.78 2.29,1.78, body extent -2.26,-1.76 2.26,1.76, height 0.84
PWRM-TH_BXXXXS-2WR3 [mm]
  rect 1.8x1.8 hole 1: 1(-6.35,0)
  round 1.8 hole 1: 2(-3.81,0) 4(1.27,0) 6(6.35,0)
  silkscreen extent -8.56,-6.15 11.1,0.9, body extent -8.43,-6.19 11.22,0.86, height 10.16
QFN-28_L4.0-W4.0-P0.40-BL-EP2.7 [mm]
  rect 0.2x0.7 smd paste-100: 1(-1.2,-2) 2(-0.8,-2) 3(-0.4,-2) 4(-0.001,-2) 5(0.4,-2) 6(0.8,-2) 7(1.2,-2) 15(1.2,2) 16(0.8,2) 17(0.4,2) 18(0,2) 19(-0.4,2) 20(-0.8,2) 21(-1.2,2)
  rect 0.7x0.2 smd paste-100: 8(2,-1.2) 9(2,-0.8) 10(2,-0.4) 11(1.999,0) 12(2,0.4) 13(2,0.8) 14(2,1.2) 22(-2,1.2) 23(-2,0.8) 24(-2,0.4) 25(-2,0) 26(-2,-0.4) 27(-2,-0.8) 28(-2,-1.2)
  rect 2.7x2.7 smd paste-100: 29(0,0)
  silkscreen extent -2.22,-2.21 2,2, body extent -2.01,-2.01 2.01,2.01, height 0.73
QFN-40_L5.0-W5.0-P0.40-BL-EP3.7 [mm]
  rect 0.2x0.8 smd paste-100: 1(-1.8,-2.499) 2(-1.4,-2.499) 3(-1,-2.499) 4(-0.6,-2.499) 5(-0.2,-2.499) 6(0.2,-2.499) 7(0.6,-2.499) 8(1,-2.499) 9(1.4,-2.499) 10(1.8,-2.499) 21(1.8,2.499) 22(1.4,2.499) 23(1,2.499) 24(0.6,2.499) 25(0.2,2.499) 26(-0.2,2.499) 27(-0.6,2.499) 28(-1,2.499) 29(-1.4,2.499) 30(-1.8,2.499)
  rect 0.8x0.2 smd paste-100: 11(2.499,-1.8) 12(2.499,-1.4) 13(2.499,-1) 14(2.499,-0.6) 15(2.499,-0.2) 16(2.499,0.2) 17(2.499,0.6) 18(2.499,1) 19(2.499,1.4) 20(2.499,1.8) 31(-2.499,1.8) 32(-2.499,1.4) 33(-2.499,1) 34(-2.499,0.6) 35(-2.499,0.2) 36(-2.499,-0.2) 37(-2.499,-0.6) 38(-2.499,-1) 39(-2.499,-1.4) 40(-2.499,-1.8)
  rect 3.7x3.7 smd paste-100: 41(0,0)
  silkscreen extent -2.7,-3.35 2.7,2.7
QFN-76_L9.0-W9.0-P0.40-EP6.3-TL [mm]
  oval 0.8x0.2 smd paste-100: 1(-4.45,3.599) 2(-4.45,3.2) 3(-4.45,2.799) 4(-4.45,2.4) 5(-4.45,1.999) 6(-4.45,1.6) 7(-4.45,1.199) 8(-4.45,0.8) 9(-4.45,0.399) 10(-4.45,0) 11(-4.45,-0.399) 12(-4.45,-0.8) 13(-4.45,-1.199) 14(-4.45,-1.6) 15(-4.45,-1.999) 16(-4.45,-2.4) 17(-4.45,-2.799) 18(-4.45,-3.2) 19(-4.45,-3.599) 39(4.45,-3.599) 40(4.45,-3.2) 41(4.45,-2.799) 42(4.45,-2.4) 43(4.45,-1.999) 44(4.45,-1.6) 45(4.45,-1.199) 46(4.45,-0.8) 47(4.45,-0.399) 48(4.45,0) 49(4.45,0.399) 50(4.45,0.8) 51(4.45,1.199) 52(4.45,1.6) 53(4.45,1.999) 54(4.45,2.4) 55(4.45,2.799) 56(4.45,3.2) 57(4.45,3.599)
  oval 0.2x0.8 smd paste-100: 20(-3.599,-4.45) 21(-3.2,-4.45) 22(-2.799,-4.45) 23(-2.4,-4.45) 24(-1.999,-4.45) 25(-1.6,-4.45) 26(-1.199,-4.45) 27(-0.8,-4.45) 28(-0.399,-4.45) 29(0,-4.45) 30(0.399,-4.45) 31(0.8,-4.45) 32(1.199,-4.45) 33(1.6,-4.45) 34(1.999,-4.45) 35(2.4,-4.45) 36(2.799,-4.45) 37(3.2,-4.45) 38(3.599,-4.45) 58(3.599,4.45) 59(3.2,4.45) 60(2.799,4.45) 61(2.4,4.45) 62(1.999,4.45) 63(1.6,4.45) 64(1.199,4.45) 65(0.8,4.45) 66(0.399,4.45) 67(0,4.45) 68(-0.399,4.45) 69(-0.8,4.45) 70(-1.199,4.45) 71(-1.6,4.45) 72(-1.999,4.45) 73(-2.4,4.45) 74(-2.799,4.45) 75(-3.2,4.45) 76(-3.599,4.45)
  rect 6.5x6.5 smd paste-100: 77(0,0)
  silkscreen extent -5.36,-4.7 4.7,4.7, body extent -4.5,-4.5 4.5,4.5, height 0.85
"R 0201_L" [mm] "1/20W贴片电阻"
  rect 0.25x0.3 smd: 1(-0.25,0) 2(0.25,0)
  silkscreen extent -0.53,-0.3 0.53,0.3, body extent -0.3,-0.15 0.3,0.15, height 0.23
"R 0402_L" [mm] "1/16W贴片电阻"
  rect 0.4x0.5 smd: 1(-0.45,0) 2(0.45,0)
  silkscreen extent -0.85,-0.45 0.85,0.45, body extent -0.5,-0.25 0.5,0.25, height 0.3
"R 0603_L" [mil] "1/10W贴片电阻"
  rect 30x30 smd: 1(-30.59,0) 2(30.59,0)
  silkscreen extent -55,-24 55,24, body extent -31,-16 31,16, height 16
"R 0805_L" [mil]
  rect 35x50 smd: 1(-37.4,0) 2(37.4,0)
  silkscreen extent -64,-34 64,34, body extent -39,-25 39,25, height 20
RJ45-TH_HR911130A [mil]
  round 66.93 hole 43.31: 11(260.83,271.46) 12(160.83,271.46) 13(-160.83,271.46) 14(-260.83,271.46)
  rect 60x60 hole 35.83: P1(225.2,-271.45)
  round 60 hole 35.83: P2(179.1,-171.45) P3(125.2,-271.45) P4(79.1,-171.45) P5(25.2,-271.45) P6(-20.9,-171.45) P7(-74.8,-271.45) P8(-120.9,-171.45) P9(-174.8,-271.45) P10(-220.9,-171.45)
  round 85 hole 66.93: SHIELD0(-304.92,-41.55) SHIELD1(304.92,-41.55)
  Keep-Out Layer board cut-out: -161.02,78.55 -161.02,72.24 -163.48,59.88 -168.31,48.24 -175.31,37.76 -184.22,28.85 -194.7,21.85 -206.34,17.03 -218.7,14.57 -231.3,14.57 -243.66,17.03 -255.3,21.85 -265.78,28.85 -274.69,37.76 -281.69,48.24 -286.52,59.88 -288.98,72.24 -288.98,78.55 -288.98,84.85 -286.52,97.21 -281.69,108.85 -274.69,119.33 -265.78,128.24 -255.3,135.24 -243.66,140.06 -231.3,142.52 -218.7,142.52 -206.34,140.06 -194.7,135.24 -184.22,128.24 -175.31,119.33 -168.31,108.85 -163.48,97.21 -161.02,84.85 -161.02,78.55 -161.02,78.55
  Keep-Out Layer board cut-out: 288.98,78.55 288.98,72.24 286.52,59.88 281.69,48.24 274.69,37.76 265.78,28.85 255.3,21.85 243.66,17.03 231.3,14.57 218.7,14.57 206.34,17.03 194.7,21.85 184.22,28.85 175.31,37.76 168.31,48.24 163.48,59.88 161.02,72.24 161.02,78.55 161.02,84.85 163.48,97.21 168.31,108.85 175.31,119.33 184.22,128.24 194.7,135.24 206.34,140.06 218.7,142.52 231.3,142.52 243.66,140.06 255.3,135.24 265.78,128.24 274.69,119.33 281.69,108.85 286.52,97.21 288.98,84.85 288.98,78.55 288.98,78.55
  Keep-Out Layer circle w0.1: c-225,78.55 r63.98
  Keep-Out Layer circle w0.1: c225,78.55 r63.98
  Keep-Out Layer region: -161.02,78.55 -161.02,72.24 -163.48,59.88 -168.31,48.24 -175.31,37.76 -184.22,28.85 -194.7,21.85 -206.34,17.03 -218.7,14.57 -231.3,14.57 -243.66,17.03 -255.3,21.85 -265.78,28.85 -274.69,37.76 -281.69,48.24 -286.52,59.88 -288.98,72.24 -288.98,78.55 -288.98,84.85 -286.52,97.21 -281.69,108.85 -274.69,119.33 -265.78,128.24 -255.3,135.24 -243.66,140.06 -231.3,142.52 -218.7,142.52 -206.34,140.06 -194.7,135.24 -184.22,128.24 -175.31,119.33 -168.31,108.85 -163.48,97.21 -161.02,84.85 -161.02,78.55 -161.02,78.55
  Keep-Out Layer region: -161.02,78.55 -161.4,71.63 -162.52,64.79 -164.37,58.12 -166.94,51.68 -170.18,45.56 -174.07,39.83 -178.55,34.55 -183.58,29.78 -189.1,25.59 -195.03,22.02 -201.32,19.11 -207.88,16.9 -214.65,15.41 -221.54,14.66 -228.46,14.66 -235.35,15.41 -242.12,16.9 -248.68,19.11 -254.97,22.02 -260.9,25.59 -266.42,29.78 -271.45,34.55 -275.93,39.83 -279.82,45.56 -283.06,51.68 -285.63,58.12 -287.48,64.79 -288.6,71.63 -288.98,78.55 -288.6,85.46 -287.48,92.3 -285.63,98.97 -283.06,105.41 -279.82,111.53 -275.93,117.26 -271.45,122.54 -266.42,127.31 -260.9,131.5 -254.97,135.07 -248.68,137.98 -242.12,140.19 -235.35,141.68 -228.46,142.43 -221.54,142.43 -214.65,141.68 -207.88,140.19 -201.32,137.98 -195.03,135.07 -189.1,131.5 -183.58,127.31 -178.55,122.54 -174.07,117.26 -170.18,111.53 -166.94,105.41 -164.37,98.97 -162.52,92.3 -161.4,85.46 -161.02,78.55
  Keep-Out Layer region: 288.98,78.55 288.98,72.24 286.52,59.88 281.69,48.24 274.69,37.76 265.78,28.85 255.3,21.85 243.66,17.03 231.3,14.57 218.7,14.57 206.34,17.03 194.7,21.85 184.22,28.85 175.31,37.76 168.31,48.24 163.48,59.88 161.02,72.24 161.02,78.55 161.02,84.85 163.48,97.21 168.31,108.85 175.31,119.33 184.22,128.24 194.7,135.24 206.34,140.06 218.7,142.52 231.3,142.52 243.66,140.06 255.3,135.24 265.78,128.24 274.69,119.33 281.69,108.85 286.52,97.21 288.98,84.85 288.98,78.55 288.98,78.55
  Keep-Out Layer region: 288.98,78.55 288.6,71.63 287.48,64.79 285.63,58.12 283.06,51.68 279.82,45.56 275.93,39.83 271.45,34.55 266.42,29.78 260.9,25.59 254.97,22.02 248.68,19.11 242.12,16.9 235.35,15.41 228.46,14.66 221.54,14.66 214.65,15.41 207.88,16.9 201.32,19.11 195.03,22.02 189.1,25.59 183.58,29.78 178.55,34.55 174.07,39.83 170.18,45.56 166.94,51.68 164.37,58.12 162.52,64.79 161.4,71.63 161.02,78.55 161.4,85.46 162.52,92.3 164.37,98.97 166.94,105.41 170.18,111.53 174.07,117.26 178.55,122.54 183.58,127.31 189.1,131.5 195.03,135.07 201.32,137.98 207.88,140.19 214.65,141.68 221.54,142.43 228.46,142.43 235.35,141.68 242.12,140.19 248.68,137.98 254.97,135.07 260.9,131.5 266.42,127.31 271.45,122.54 275.93,117.26 279.82,111.53 283.06,105.41 285.63,98.97 287.48,92.3 288.6,85.46 288.98,78.55
  silkscreen extent -316,-331 316,508, body extent -320,-334 315,504, height 531
SOT-23-5_L3.0-W1.7-P0.95-LS2.8-BL [mil]
  rect 19.3x45.6 smd: 1(-37.4,-45.4) 2(0,-45.4) 3(37.4,-45.4)
  rect 19.3x46.3 smd: 4(37.4,45.5) 5(-37.4,45.5)
  silkscreen extent -71,-51 60,34
SOT-23-5_L3.0-W1.7-P0.95-LS2.8-BR [mm]
  rect 1.1x0.6 smd: 1(1.3,-0.95) 2(1.3,0) 3(1.3,0.95) 4(-1.3,0.95) 5(-1.3,-0.95)
  silkscreen extent -0.9,-1.55 0.9,1.55, body extent -1.51,-1.45 1.51,1.45, height 1.2
SOT-563-6_L1.6-W1.2-P0.5-LS1.6-BL [mm]
  rect 0.28x0.68 smd: 1(-0.5,-0.64) 2(0,-0.64) 3(0.5,-0.64) 4(0.5,0.64) 5(0,0.64) 6(-0.5,0.64)
  silkscreen extent -1.02,-1.02 0.88,0.68, body extent -0.8,-0.8 0.8,0.8, height 0.56
TSSOP-20_L6.5-W4.4-P0.65-LS6.4-BL [mil]
  oval 14.33x68.58 smd: 1(-115.16,-113.03) 2(-89.57,-113.03) 3(-63.98,-113.03) 4(-38.39,-113.03) 5(-12.79,-113.03) 6(12.8,-113.03) 7(38.39,-113.03) 8(63.98,-113.03) 9(89.57,-113.03) 10(115.16,-113.03) 11(115.16,113.03) 12(89.57,113.03) 13(63.98,113.03) 14(38.39,113.03) 15(12.8,113.03) 16(-12.79,113.03) 17(-38.39,113.03) 18(-63.98,113.03) 19(-89.57,113.03) 20(-115.16,113.03)
  silkscreen extent -146,-119 131,70
TYPE-C-SMD_TYPE-C-24P-QCHT [mm]
  oval 1x1.6 hole 0.6 slot 1.2 at 90 deg paste-2539.97: 25(-4.49,-3.158) 25(-4.13,1.233) 25(4.13,1.233) 25(4.49,-3.158)
  rect 0.275x1.25 smd paste-100: A1(-2.79,3.158) A2(-2.25,3.158) A3(-1.75,3.158) A4(-1.25,3.158) A5(-0.75,3.158) A6(-0.25,3.158) A7(0.25,3.158) A8(0.75,3.158) A9(1.25,3.158) A10(1.75,3.158) A11(2.25,3.158) A12(2.75,3.158)
  round 0.6 hole 0.4 paste-2539.97: B1(2.8,1.832) B2(2.4,1.132) B3(1.6,1.133) B4(1.2,1.832) B5(0.8,1.133) B6(0.4,1.833) B7(-0.4,1.832) B8(-0.8,1.132) B9(-1.2,1.833) B10(-1.6,1.133) B11(-2.4,1.132) B12(-2.8,1.833)
  Keep-Out Layer board cut-out: 4.075,2.483 4.075,2.403 4.014,2.256 3.902,2.144 3.755,2.083 3.595,2.083 3.448,2.144 3.336,2.256 3.275,2.403 3.275,2.483 3.275,2.563 3.336,2.71 3.448,2.822 3.595,2.883 3.755,2.883 3.902,2.822 4.014,2.71 4.075,2.563 4.075,2.483 4.075,2.483
  Keep-Out Layer board cut-out: -3.275,2.483 -3.275,2.403 -3.336,2.256 -3.448,2.144 -3.595,2.083 -3.755,2.083 -3.902,2.144 -4.014,2.256 -4.075,2.403 -4.075,2.483 -4.075,2.563 -4.014,2.71 -3.902,2.822 -3.755,2.883 -3.595,2.883 -3.448,2.822 -3.336,2.71 -3.275,2.563 -3.275,2.483 -3.275,2.483
  Keep-Out Layer circle w0.003: c3.675,2.483 r0.4
  Keep-Out Layer circle w0.003: c-3.675,2.483 r0.4
  Keep-Out Layer region: 4.075,2.483 4.065,2.394 4.035,2.309 3.988,2.234 3.924,2.17 3.849,2.123 3.764,2.093 3.675,2.083 3.586,2.093 3.501,2.123 3.426,2.17 3.362,2.234 3.315,2.309 3.285,2.394 3.275,2.483 3.285,2.572 3.315,2.657 3.362,2.732 3.426,2.796 3.501,2.843 3.586,2.873 3.675,2.883 3.764,2.873 3.849,2.843 3.924,2.796 3.988,2.732 4.035,2.657 4.065,2.572 4.075,2.483
  Keep-Out Layer region: 4.075,2.483 4.075,2.403 4.014,2.256 3.902,2.144 3.755,2.083 3.595,2.083 3.448,2.144 3.336,2.256 3.275,2.403 3.275,2.483 3.275,2.563 3.336,2.71 3.448,2.822 3.595,2.883 3.755,2.883 3.902,2.822 4.014,2.71 4.075,2.563 4.075,2.483 4.075,2.483
  Keep-Out Layer region: -3.275,2.483 -3.285,2.394 -3.315,2.309 -3.362,2.234 -3.426,2.17 -3.501,2.123 -3.586,2.093 -3.675,2.083 -3.764,2.093 -3.849,2.123 -3.924,2.17 -3.988,2.234 -4.035,2.309 -4.065,2.394 -4.075,2.483 -4.065,2.572 -4.035,2.657 -3.988,2.732 -3.924,2.796 -3.849,2.843 -3.764,2.873 -3.675,2.883 -3.586,2.873 -3.501,2.843 -3.426,2.796 -3.362,2.732 -3.315,2.657 -3.285,2.572 -3.275,2.483
  Keep-Out Layer region: -3.275,2.483 -3.275,2.403 -3.336,2.256 -3.448,2.144 -3.595,2.083 -3.755,2.083 -3.902,2.144 -4.014,2.256 -4.075,2.403 -4.075,2.483 -4.075,2.563 -4.014,2.71 -3.902,2.822 -3.755,2.883 -3.595,2.883 -3.448,2.822 -3.336,2.71 -3.275,2.563 -3.275,2.483 -3.275,2.483
  silkscreen extent -4.46,-5.69 4.46,4.16, body extent -4.82,-5.69 4.82,4.16, height 2.98
USB3.0-A-TH_HC-USB3.0-L168-ZJ [mm]
  round 1.3 hole 0.8: 1(-3.5,0.3) 2(-1,0.3) 3(1,0.3) 4(3.5,0.3) 5(4,1.8) 6(2,1.8) 7(0,1.8) 8(-2,1.8) 9(-4,1.8)
  oval 1.2x3.2 hole 0.6 slot 2.415 at 90 deg: 10(6.4,-1.8) 11(-6.4,-1.8)
  silkscreen extent -7,-13.6 7,3.3, body extent -7.2,-13.48 7.2,3.32, height 7.65
USB-A-TH_AF-WJDG [mm]
  round 1.52 hole 0.92 paste-2539.97: 1(-3.5,1.355) 2(-1,1.355) 3(1,1.355) 4(3.5,1.355)
  round 3.2 hole 2.3 paste-2539.97: 5(-6.57,-1.355) 5(6.57,-1.355)
  silkscreen extent -7.2,-11.66 7.2,2.46, body extent -7.75,-12.08 7.75,1.92, height 7.64
VQFN-HR-10_L3.0-W3.0_RPA [mm]
  rect 0.6x0.25 smd paste-100: 1(-1.36,0.75) 2(-1.36,0.25) 3(-1.36,-0.25) 4(-1.36,-0.75)
  rect 0.25x0.6 smd paste-100: 5(-0.89,-1.4) 7(0.91,-1.4) 10(-0.89,1.4)
  rect 0.25x1.7 smd paste-100: 6(0.41,-0.85)
  rect 0.4x2.1 smd paste-100: 8(0.99,0.65) 9(-0.17,0.65)
  rect 0.8x0.25 smd paste-100: 8(1.36,-0.25) 8(1.36,0.25) 8(1.36,0.75)
  silkscreen extent -1.87,-1.55 1.55,1.55
VQFN-HR-12_L2.5-W2.0-P0.50-BL [mm]
  rect 0.4x1.05 smd: 1(-0.35,-0.675)
  oval 0.4x1.05 smd: 2(0.35,-0.675) 7(0.35,0.675) 8(-0.35,0.675)
  oval 0.6x0.2 smd: 3(1.15,-0.75) 4(1.15,-0.25) 5(1.15,0.25) 6(1.15,0.75) 9(-1.15,0.75) 10(-1.15,0.25) 11(-1.15,-0.25) 12(-1.15,-0.75)
  silkscreen extent -1.25,-1.6 1.25,1.1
